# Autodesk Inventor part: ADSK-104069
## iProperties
Shininess: 0.0
Created: 2000-10
Part Number: ADSK-104069
Document SubType Name: Modeling
Stock Number: ADSK-104069
Density: 1 g/cm^3
Density: 0.0
Volumn: 0.0
Area: 0.0
PropertySet Name: Model Information
Control State: 0
Master: False
Checked Out: False
Author: gao
